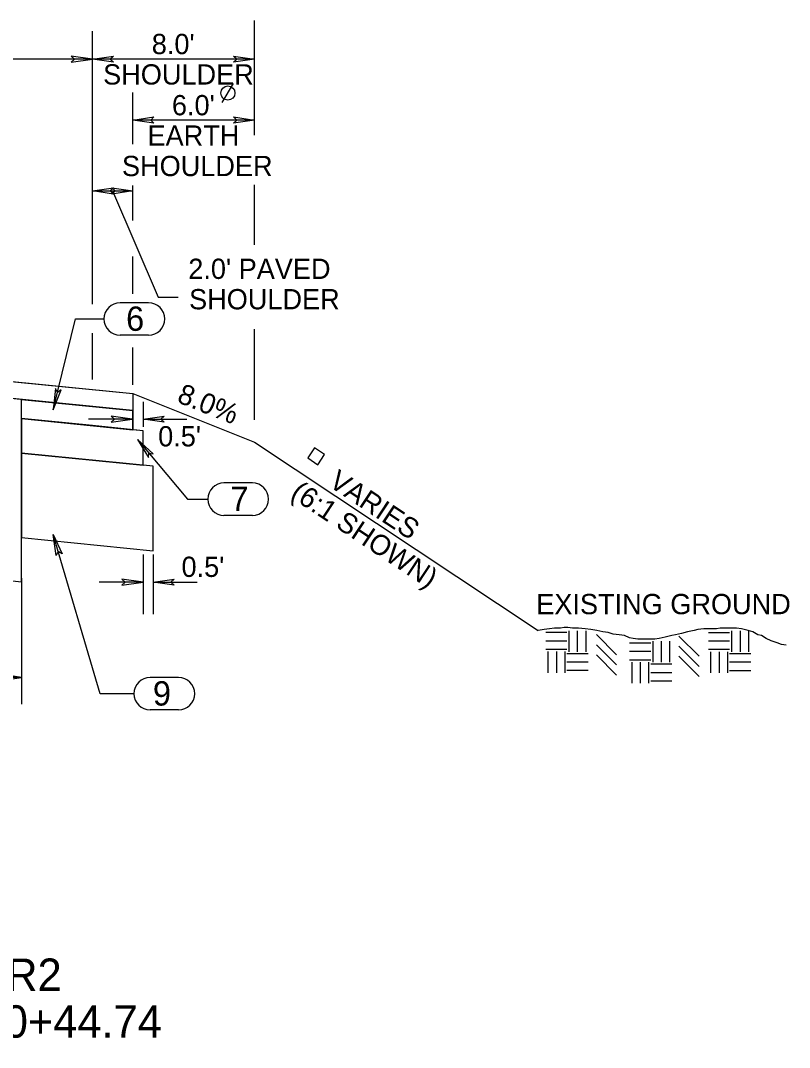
# Model space of a CAD drawing. Extents: x 2003207 to 2014043, y 843846 to 860154.
# Drawn here: x 2013907.8 to 2013945.8, y 844586.7 to 844637.3 of the extents above; entities that cross this region are included whole.
import ezdxf

# ---------------------------------------------------------------- set-up
doc = ezdxf.new("R2010")
doc.units = 0
for name, color, linetype in [('RD_EX_Road', 7, 'Continuous'), ('RD_EX_Road_txCode', 7, 'Continuous'), ('RD_QTY_Base_Course', 7, 'Continuous'), ('RD_QTY_ConcPave', 7, 'Continuous'), ('RD_QTY_Intermediate', 7, 'Continuous'), ('RD_QTY_PermVeg', 7, 'Continuous'), ('RD_QTY_Surf_Course', 7, 'Continuous'), ('RD_TX_Misc2', 7, 'Continuous'), ('RD_TX_TypSect', 7, 'Continuous'), ('RD_XS_ExGround', 7, 'Continuous')]:
    doc.layers.add(name, color=color, linetype=linetype)

msp = doc.modelspace()

# ---------------------------------------------------------------- linework, layer by layer
at = {"layer": 'RD_EX_Road'}
for p, q in [((2013907.892, 844618.653), (2013895.892, 844619.853)), ((2013907.892, 844609.657), (2013907.892, 844618.653)), ((2013897.722, 844610.705), (2013907.892, 844609.657))]:
    msp.add_line(p, q, dxfattribs=at)
at = {"layer": 'RD_EX_Road_txCode'}
msp.add_lwpolyline([(2013922.015, 844615.762), (2013922.515, 844615.431), (2013922.846, 844615.931), (2013922.346, 844616.263)], close=True, dxfattribs=at)
at = {"layer": 'RD_QTY_Base_Course'}
for p, q in [((2013911.392, 844617.356), (2013907.892, 844617.706)), ((2013907.892, 844617.706), (2013907.892, 844616.001)), ((2013913.892, 844617.106), (2013911.392, 844617.356)), ((2013913.892, 844615.401), (2013913.892, 844617.106)), ((2013907.892, 844616.001), (2013913.892, 844615.401)), ((2013911.892, 844615.601), (2013907.892, 844616.001)), ((2013907.892, 844616.001), (2013907.892, 844611.834)), ((2013914.392, 844615.351), (2013911.892, 844615.601)), ((2013914.392, 844615.351), (2013913.892, 844615.401)), ((2013914.392, 844611.184), (2013914.392, 844615.351)), ((2013914.392, 844611.184), (2013914.392, 844615.351)), ((2013907.892, 844611.834), (2013914.392, 844611.184)), ((2013907.892, 844611.834), (2013914.392, 844611.184))]:
    msp.add_line(p, q, dxfattribs=at)
at = {"layer": 'RD_QTY_ConcPave'}
for p, q in [((2013913.892, 844617.106), (2013913.392, 844617.156)), ((2013913.892, 844615.401), (2013913.892, 844617.106)), ((2013907.892, 844616.001), (2013913.892, 844615.401))]:
    msp.add_line(p, q, dxfattribs=at)
at = {"layer": 'RD_QTY_Intermediate'}
for p, q in [((2013913.392, 844617.156), (2013913.392, 844618.103)), ((2013907.892, 844617.706), (2013913.392, 844617.156))]:
    msp.add_line(p, q, dxfattribs=at)
msp.add_lwpolyline([(2013913.392, 844618.103), (2013913.392, 844617.156), (2013907.892, 844617.706), (2013907.892, 844618.653)], close=True, dxfattribs=at)
at = {"layer": 'RD_QTY_PermVeg'}
for p, q in [((2013913.392, 844618.936), (2013919.392, 844616.536)), ((2013919.392, 844616.536), (2013933.392, 844607.258))]:
    msp.add_line(p, q, dxfattribs=at)
at = {"layer": 'RD_QTY_Surf_Course'}
for p, q in [((2013891.892, 844621.086), (2013913.392, 844618.936)), ((2013891.892, 844620.253), (2013913.392, 844618.103)), ((2013913.392, 844618.936), (2013913.392, 844618.103))]:
    msp.add_line(p, q, dxfattribs=at)
msp.add_lwpolyline([(2013870.392, 844618.936), (2013891.892, 844621.086), (2013913.392, 844618.936), (2013913.392, 844618.103), (2013895.892, 844619.853), (2013891.892, 844619.453), (2013891.892, 844620.253), (2013870.392, 844618.103)], close=True, dxfattribs=at)
at = {"layer": 'RD_TX_Misc2'}
for p, q in [((2013914.164, 844623.419), (2013912.764, 844623.419)), ((2013914.164, 844621.819), (2013912.764, 844621.819)), ((2013919.286, 844614.529), (2013917.886, 844614.529)), ((2013919.286, 844612.929), (2013917.886, 844612.929)), ((2013915.643, 844604.934), (2013914.243, 844604.934)), ((2013915.643, 844603.334), (2013914.243, 844603.334))]:
    msp.add_line(p, q, dxfattribs=at)
for centre, start, end in [((2013912.764, 844622.619), 90, 270), ((2013914.164, 844622.619), 270, 90), ((2013917.886, 844613.729), 90, 270), ((2013919.286, 844613.729), 270, 90), ((2013914.243, 844604.134), 90, 270), ((2013915.643, 844604.134), 270, 90)]:
    msp.add_arc(centre, 0.8, start, end, dxfattribs=at)
at = {"layer": 'RD_TX_TypSect'}
for p, q in [((2013919.392, 844631.683), (2013919.392, 844637.34)), ((2013911.392, 844623.349), (2013911.392, 844636.824)), ((2013911.392, 844635.433), (2013899.392, 844635.433)), ((2013919.392, 844635.433), (2013911.392, 844635.433)), ((2013917.795, 844633.29), (2013918.361, 844634.233)), ((2013913.392, 844631.248), (2013913.392, 844633.787)), ((2013919.392, 844632.433), (2013913.392, 844632.433)), ((2013913.392, 844627.476), (2013913.392, 844629.206)), ((2013919.392, 844626.276), (2013919.392, 844629.234)), ((2013911.392, 844628.933), (2013913.392, 844628.933)), ((2013913.392, 844623.854), (2013913.392, 844625.696)), ((2013911.392, 844619.636), (2013911.392, 844621.914)), ((2013919.392, 844617.649), (2013919.392, 844622.124)), ((2013913.392, 844619.362), (2013913.392, 844621.204)), ((2013913.892, 844618.53), (2013913.892, 844617.302)), ((2013913.362, 844617.671), (2013911.195, 844617.671)), ((2013913.892, 844617.671), (2013916.06, 844617.671)), ((2013913.892, 844611.002), (2013913.892, 844608.061)), ((2013914.392, 844611.002), (2013914.392, 844608.061)), ((2013907.892, 844609.828), (2013907.892, 844603.621)), ((2013913.892, 844609.63), (2013911.725, 844609.63)), ((2013914.392, 844609.63), (2013916.56, 844609.63)), ((2013907.892, 844604.939), (2013883.892, 844604.939))]:
    msp.add_line(p, q, dxfattribs=at)
for points in [[(2013911.392, 844635.433), (2013910.354, 844635.583), (2013910.514, 844635.433), (2013910.354, 844635.283)], [(2013911.392, 844635.433), (2013912.431, 844635.583), (2013912.271, 844635.433), (2013912.431, 844635.283)], [(2013919.392, 844635.433), (2013918.354, 844635.283), (2013918.514, 844635.433), (2013918.354, 844635.583)], [(2013913.392, 844632.433), (2013914.431, 844632.583), (2013914.271, 844632.433), (2013914.431, 844632.283)], [(2013919.392, 844632.433), (2013918.354, 844632.283), (2013918.514, 844632.433), (2013918.354, 844632.583)], [(2013911.392, 844628.933), (2013912.431, 844629.083), (2013912.271, 844628.933), (2013912.431, 844628.783)], [(2013913.392, 844628.933), (2013912.354, 844628.783), (2013912.514, 844628.933), (2013912.354, 844629.083)], [(2013909.466, 844618.144), (2013909.858, 844619.117), (2013909.674, 844618.997), (2013909.567, 844619.188)], [(2013913.362, 844617.671), (2013912.324, 844617.82), (2013912.484, 844617.671), (2013912.324, 844617.521)], [(2013913.892, 844617.671), (2013914.931, 844617.82), (2013914.771, 844617.671), (2013914.931, 844617.521)], [(2013913.617, 844616.675), (2013914.168, 844615.782), (2013914.18, 844616.001), (2013914.398, 844615.974)], [(2013909.459, 844611.989), (2013909.897, 844611.035), (2013909.708, 844611.146), (2013909.609, 844610.95)], [(2013913.892, 844609.63), (2013912.854, 844609.78), (2013913.014, 844609.63), (2013912.854, 844609.48)], [(2013914.392, 844609.63), (2013915.431, 844609.78), (2013915.271, 844609.63), (2013915.431, 844609.48)], [(2013907.892, 844604.939), (2013906.854, 844605.089), (2013907.014, 844604.939), (2013906.854, 844604.789)]]:
    msp.add_lwpolyline(points, close=True, dxfattribs=at)
for points in [[(2013912.392, 844628.933), (2013914.632, 844623.687), (2013915.62, 844623.687)], [(2013909.466, 844618.144), (2013910.561, 844622.619), (2013911.964, 844622.619)], [(2013913.617, 844616.675), (2013916.078, 844613.729), (2013917.086, 844613.729)], [(2013913.443, 844604.134), (2013911.778, 844604.134), (2013909.459, 844611.989)]]:
    msp.add_lwpolyline(points, dxfattribs=at)
msp.add_circle((2013918.078, 844633.762), 0.35, dxfattribs=at)
at = {"layer": 'RD_XS_ExGround'}
for p, q in [((2013934.902, 844607.242), (2013934.902, 844606.201)), ((2013935.319, 844607.242), (2013935.319, 844606.201)), ((2013935.735, 844607.242), (2013935.735, 844606.201)), ((2013942.929, 844607.237), (2013942.929, 844606.196)), ((2013943.346, 844607.237), (2013943.346, 844606.196)), ((2013943.762, 844607.237), (2013943.762, 844606.196)), ((2013934.806, 844607.145), (2013933.764, 844607.145)), ((2013934.806, 844606.729), (2013933.764, 844606.729)), ((2013937.258, 844606.051), (2013936.258, 844607.051)), ((2013939.038, 844606.724), (2013939.038, 844605.682)), ((2013939.455, 844606.724), (2013939.455, 844605.682)), ((2013939.872, 844606.724), (2013939.872, 844605.682)), ((2013941.326, 844605.978), (2013940.326, 844606.978)), ((2013942.832, 844607.141), (2013941.791, 844607.141)), ((2013942.832, 844606.724), (2013941.791, 844606.724)), ((2013934.806, 844606.312), (2013933.764, 844606.312)), ((2013933.868, 844606.208), (2013933.868, 844605.166)), ((2013934.285, 844606.208), (2013934.285, 844605.166)), ((2013934.702, 844606.208), (2013934.702, 844605.166)), ((2013937.258, 844605.551), (2013936.258, 844606.551)), ((2013938.942, 844606.627), (2013937.9, 844606.627)), ((2013938.942, 844606.21), (2013937.9, 844606.21)), ((2013941.326, 844605.478), (2013940.326, 844606.478)), ((2013942.832, 844606.307), (2013941.791, 844606.307)), ((2013941.895, 844606.203), (2013941.895, 844605.161)), ((2013942.312, 844606.203), (2013942.312, 844605.161)), ((2013942.728, 844606.203), (2013942.728, 844605.161)), ((2013935.847, 844606.104), (2013934.806, 844606.104)), ((2013935.847, 844605.687), (2013934.806, 844605.687)), ((2013937.258, 844605.051), (2013936.258, 844606.051)), ((2013938.942, 844605.793), (2013937.9, 844605.793)), ((2013938.004, 844605.689), (2013938.004, 844604.648)), ((2013938.421, 844605.689), (2013938.421, 844604.648)), ((2013938.838, 844605.689), (2013938.838, 844604.648)), ((2013941.326, 844604.978), (2013940.326, 844605.978)), ((2013943.874, 844606.099), (2013942.832, 844606.099)), ((2013943.874, 844605.682), (2013942.832, 844605.682)), ((2013935.847, 844605.27), (2013934.806, 844605.27)), ((2013939.984, 844605.585), (2013938.942, 844605.585)), ((2013939.984, 844605.168), (2013938.942, 844605.168)), ((2013943.874, 844605.266), (2013942.832, 844605.266)), ((2013939.984, 844604.752), (2013938.942, 844604.752))]:
    msp.add_line(p, q, dxfattribs=at)
msp.add_lwpolyline([(2013945.618, 844606.525), (2013945.399, 844606.562), (2013945.179, 844606.635), (2013944.886, 844606.745), (2013944.63, 844606.855), (2013944.41, 844607.001), (2013944.227, 844607.038), (2013943.971, 844607.185), (2013943.751, 844607.258), (2013943.422, 844607.331), (2013943.166, 844607.368), (2013942.873, 844607.368), (2013942.543, 844607.368), (2013942.36, 844607.368), (2013942.177, 844607.331), (2013941.958, 844607.331), (2013941.738, 844607.331), (2013941.555, 844607.331), (2013941.262, 844607.294), (2013941.079, 844607.258), (2013940.75, 844607.185), (2013940.457, 844607.111), (2013940.164, 844607.038), (2013939.981, 844607.001), (2013939.652, 844606.928), (2013939.359, 844606.855), (2013939.139, 844606.818), (2013938.956, 844606.818), (2013938.737, 844606.818), (2013938.517, 844606.818), (2013938.297, 844606.818), (2013938.078, 844606.855), (2013937.895, 844606.892), (2013937.638, 844607.001), (2013937.382, 844607.038), (2013937.089, 844607.075), (2013936.833, 844607.148), (2013936.577, 844607.185), (2013936.284, 844607.258), (2013935.991, 844607.294), (2013935.698, 844607.331), (2013935.369, 844607.368), (2013935.076, 844607.368), (2013934.857, 844607.404), (2013934.674, 844607.404), (2013934.49, 844607.368), (2013934.198, 844607.368), (2013933.941, 844607.331), (2013933.685, 844607.294), (2013933.392, 844607.258)], dxfattribs=at)

# ---------------------------------------------------------------- texts
at = {"layer": 'RD_EX_Road_txCode'}
for s, p in [('US21EX (WILSON BLVD.) 720+46.38 R2 TO STA. 721+51.38 R2', (2013847.325, 844589.47)), ('FARROW (SC-555 FARROW ROAD) STA. 356+50.00 TO STA. 360+44.74', (2013843.357, 844587.164))]:
    msp.add_text(s, height=1.6, dxfattribs=at).set_placement(p)
at = {"layer": 'RD_TX_Misc2'}
for s, p in [('6', (2013913.057, 844622.034)), ('7', (2013918.202, 844613.144)), ('9', (2013914.379, 844603.549))]:
    msp.add_text(s, height=1.2, dxfattribs=at).set_placement(p)
at = {"layer": 'RD_TX_TypSect'}
for s, p in [("8.0'", (2013914.324, 844635.683)), ('SHOULDER', (2013911.924, 844634.183)), ("6.0'", (2013915.318, 844632.666)), ('EARTH', (2013914.113, 844631.166)), ('SHOULDER', (2013912.853, 844629.666)), ("2.0' PAVED", (2013916.125, 844624.594)), ('SHOULDER', (2013916.164, 844623.094)), ("0.5'", (2013914.639, 844616.332)), ("0.5'", (2013915.791, 844609.894)), ('EXISTING GROUND', (2013933.293, 844608.055))]:
    msp.add_text(s, height=1, dxfattribs=at).set_placement(p)
for s, rotation, p in [('8.0%', 338.1986, (2013915.515, 844618.535)), ('VARIES', 326.4658, (2013922.999, 844614.4)), ('(6:1 SHOWN)', 326.4658, (2013921.114, 844613.85))]:
    msp.add_text(s, height=1, rotation=rotation, dxfattribs=at).set_placement(p)

doc.saveas('drawing.dxf')
